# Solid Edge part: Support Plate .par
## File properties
Author: Dave
Template: Normal 2.par
Last saved by: Dave
Revision: 21
Application: Solid Edge
Accuracy: 0.990
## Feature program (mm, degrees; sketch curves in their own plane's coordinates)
sketch for "unnamed Protrusion 1" plane through (0, 0, 0) normal (0, 0, 1) x-axis (1, 0, 0)
  line (-87.5, -87.5) -> (87.5, -87.5)
  line (87.5, -87.5) -> (87.5, 87.5)
  line (87.5, 87.5) -> (-87.5, 87.5)
  line (-87.5, 87.5) -> (-87.5, -87.5)
  dimension (linear) = 87.5
  dimension (linear) = 87.5
extrude "unnamed Protrusion 1" add finite 27 along -normal
sketch for "Hole_1" plane through (0, 0, 0) normal (0, 0, 1) x-axis (0, 1, 0)
  hole centre (-50, 60) bore radius 5.25
  dimension (linear) = 50
hole "Hole_1" diameter 10.5 finite  VBottomAngle = 118 deg
sketch for "unnamed Hole 1" plane through (0, 0, 0) normal (0, 0, 1) x-axis (0, 1, 0)
  hole centre (50, 60) bore radius 5.25
hole "unnamed Hole 1" finite
sketch for "unnamed Hole 2" plane through (0, 0, 0) normal (0, 0, 1) x-axis (0, 1, 0)
  hole centre (50, -60) bore radius 5.25
hole "unnamed Hole 2" finite
sketch for "unnamed Hole 3" plane through (0, 0, 0) normal (0, 0, 1) x-axis (0, 1, 0)
  hole centre (-50, -60) bore radius 5.25
hole "unnamed Hole 3" finite
sketch for "unnamed Hole 4" plane through (0, 0, 0) normal (0, 0, 1) x-axis (0, 1, 0)
  hole centre (3.7644, 45.9994) bore radius 5.25
hole "unnamed Hole 4" finite
sketch for "Hole_6" plane through (0, 0, 0) normal (0, 0, 1) x-axis (-1, 0, 0)
  hole centre (45.9994, 18.0856) bore radius 1.5
hole "Hole_6" diameter 3 through  VBottomAngle = 118 deg
sketch for "unnamed Hole 5" plane through (0, 0, 0) normal (0, 0, 1) x-axis (-1, 0, 0)
  hole centre (67.6994, 2.3356) bore radius 1.5
hole "unnamed Hole 5" through
sketch for "unnamed Hole 6" plane through (0, 0, 0) normal (0, 0, 1) x-axis (-1, 0, 0)
  hole centre (39.8994, -25.4644) bore radius 1.5
hole "unnamed Hole 6" through
sketch for "unnamed Hole 7" plane through (0, 0, 0) normal (0, 0, 1) x-axis (-1, 0, 0)
  hole centre (24.1494, -3.7644) bore radius 1.5
hole "unnamed Hole 7" through
sketch for "Hole_10" plane through (0, 0, 0) normal (0, 0, 1) x-axis (-1, 0, 0)
  hole centre (0, 0) bore radius 3.25
hole "Hole_10" diameter 6.5 through  VBottomAngle = 118 deg
sketch for "Hole_11" plane through (0, 0, 0) normal (0, 0, 1) x-axis (0, 1, 0)
  hole centre (-23.4585, 65.6804) bore radius 3.25
hole "Hole_11" diameter 6.5 through  CounterBoreDepth = 6.5 mm; VBottomAngle = 118 deg
sketch for "unnamed Hole 8" plane through (0, 0, 0) normal (0, 0, 1) x-axis (0, 1, 0)
  hole centre (-23.4585, 18.7988) bore radius 3.25
hole "unnamed Hole 8" through
sketch for "unnamed Hole 9" plane through (0, 0, 0) normal (0, 0, 1) x-axis (0, 1, 0)
  hole centre (23.4454, 18.7988) bore radius 3.25
hole "unnamed Hole 9" through
sketch for "Hole_18" plane through (0, 0, -27) normal (0, 0, -1) x-axis (-1, 0, 0)
  hole centre (-15.5075, 0) bore radius 4
hole "Hole_18" nominal diameter 5 finite  VBottomAngle = 118 deg
sketch for "unnamed Hole 10" plane through (0, 0, -27) normal (0, 0, -1) x-axis (-1, 0, 0)
hole "unnamed Hole 10" finite
sketch for "Hole_20" plane through (-87.5, 0, -13.5) normal (-1, 0, 0) x-axis (0, 1, 0)
hole "Hole_20" diameter 5 finite  VBottomAngle = 118 deg
sketch for "Hole_22" plane through (-87.5, 0, -13.5) normal (-1, 0, 0) x-axis (0, -1, 0)
hole "Hole_22" diameter 8 finite  VBottomAngle = 118 deg
sketch for "Hole_23" plane through (0, 87.5, -13.5) normal (0, 1, 0) x-axis (1, 0, 0)
  hole centre (-8, 0) bore radius 2.5
hole "Hole_23" diameter 5 finite  VBottomAngle = 118 deg
pattern "unnamed Pattern 1" of "Hole_11", "unnamed Hole 8", "unnamed Hole 9"
pattern "unnamed Pattern 2" of "Hole_18", "unnamed Hole 10"
pattern "unnamed Pattern 3" of "Hole_1", "unnamed Hole 1", "unnamed Hole 2", "unnamed Hole 3", "unnamed Hole 4"
pattern "unnamed Pattern 4" of "Hole_6", "unnamed Hole 5", "unnamed Hole 6", "unnamed Hole 7"
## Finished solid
Body 1: solid body, 43 faces, 73 edges, 18 vertices.
  Faces by surface: cylinder 24, cone 10, plane 9
  Edges by curve: circle 48, line 12, ellipse 8, intersection 5
Bounding box of the edges (mm): 175.000 x 175.000 x 27.000, from (-87.5, -87.5, -27) to (87.5, 87.5, 0).
Cylindrical faces by radius (mm): R1.5 x4, R2.5 x7, R3.25 x4, R4 x1, R5.25 x5, R6.5 x3
Conical faces (half-angle, radius in mm at the cone's reference point): 59 deg R2.5 x4, 59 deg R4 x1, 59 deg R5.25 x5
Planar faces by outward normal: +x 1, +y 1, +z 4, -x 1, -y 1, -z 1
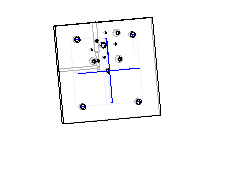
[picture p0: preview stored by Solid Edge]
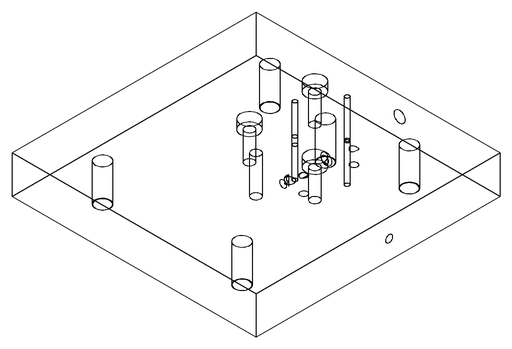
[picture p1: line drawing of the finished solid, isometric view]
